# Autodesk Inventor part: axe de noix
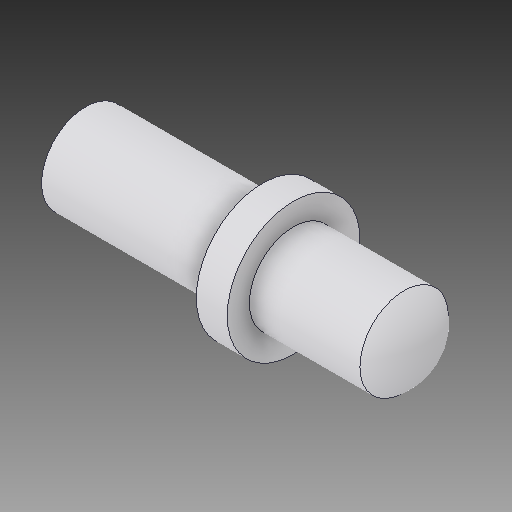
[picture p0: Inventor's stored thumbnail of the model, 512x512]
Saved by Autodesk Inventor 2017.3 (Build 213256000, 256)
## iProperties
Created: 2007-11
Part Number: axe de noix
Material: solidworks materials|Alliage 7079|22
Document SubType Name: Modeling
Designer: ficho
Density: 2.7 g/cm^3
Appearance: 227,227,233
Author: ficho
Sending System: SolidWorks 2009
Last Author: christophe
Last Saved: 2011-01-23
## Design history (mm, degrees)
feature "Dôme1"
node "Solide1"
